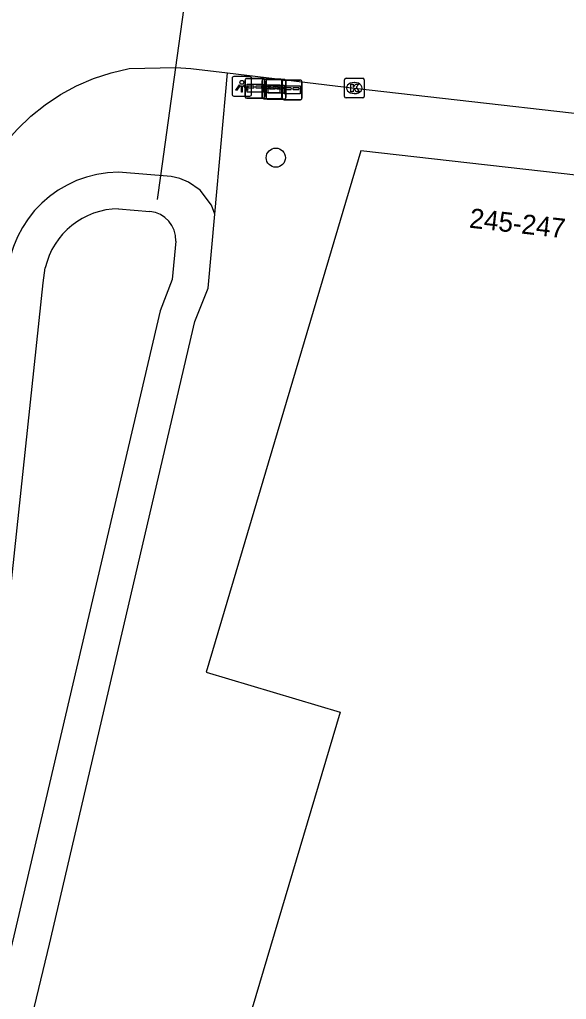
# Model space of a CAD drawing. Extents: x 161389 to 162585, y 388479 to 389761.
# Drawn here: x 162354.5 to 162382.4, y 388747.2 to 388797.2 of the extents above; entities that cross this region are included whole.
import ezdxf

# ---------------------------------------------------------------- set-up
doc = ezdxf.new("R2010")
doc.units = 0
for name, color, linetype in [('IMGEO_Berm_groen', 7, 'Continuous'), ('IMGEO_Boom', 7, 'Continuous'), ('IMGEO_Brievenbus', 7, 'Continuous'), ('IMGEO_Duiker', 7, 'Continuous'), ('IMGEO_Groenvoorziening', 7, 'Continuous'), ('IMGEO_Kolk', 7, 'Continuous'), ('IMGEO_Lichtpunt', 7, 'Continuous'), ('IMGEO_Pand', 7, 'Continuous'), ('IMGEO_Pand_nummerreeks', 7, 'Continuous'), ('IMGEO_Rijbaan_lokaal_gesloten', 7, 'Continuous'), ('IMGEO_Waterloop', 7, 'Continuous')]:
    doc.layers.add(name, color=color, linetype=linetype)

msp = doc.modelspace()

# ---------------------------------------------------------------- linework, layer by layer
at = {"layer": 'IMGEO_Berm_groen'}
for points in [[(162364.471, 388787.302), (162365.122, 388794.512)], [(162364.471, 388787.302), (162364.296, 388787.749), (162363.722, 388788.516), (162363.135, 388788.931), (162362.691, 388789.114), (162362.237, 388789.214), (162359.555, 388789.446)]]:
    msp.add_lwpolyline(points, dxfattribs=at)
msp.add_arc((162359.605, 388783.689), 5.757, 90.5023, 176.6641, dxfattribs=at)
at = {"layer": 'IMGEO_Boom'}
msp.add_circle((162367.585, 388790.182), 0.489, dxfattribs=at)
at = {"layer": 'IMGEO_Brievenbus'}
for p, q in [((162366.089, 388794.228), (162366.93, 388794.228)), ((162366.93, 388794.228), (162366.089, 388794.228)), ((162366.014, 388793.303), (162366.014, 388794.144)), ((162366.014, 388794.144), (162366.014, 388793.303)), ((162366.458, 388793.835), (162366.181, 388793.835)), ((162366.181, 388793.751), (162366.458, 388793.751)), ((162366.85, 388793.835), (162366.573, 388793.835)), ((162366.573, 388793.751), (162366.85, 388793.751)), ((162366.886, 388793.271), (162366.886, 388794.112)), ((162366.886, 388794.112), (162366.886, 388793.271)), ((162366.961, 388794.196), (162367.802, 388794.196)), ((162367.802, 388794.196), (162366.961, 388794.196)), ((162367.014, 388794.153), (162367.014, 388793.312)), ((162367.014, 388793.312), (162367.014, 388794.153)), ((162367.33, 388793.803), (162367.053, 388793.803)), ((162367.053, 388793.719), (162367.33, 388793.719)), ((162367.096, 388793.25), (162367.096, 388794.091)), ((162367.096, 388794.091), (162367.096, 388793.25)), ((162367.171, 388794.175), (162368.012, 388794.175)), ((162368.012, 388794.175), (162367.171, 388794.175)), ((162367.54, 388793.782), (162367.263, 388793.782)), ((162367.722, 388793.803), (162367.445, 388793.803)), ((162367.445, 388793.719), (162367.722, 388793.719)), ((162367.932, 388793.782), (162367.655, 388793.782)), ((162367.886, 388794.121), (162367.886, 388793.28)), ((162367.886, 388793.28), (162367.886, 388794.121)), ((162367.916, 388793.219), (162367.916, 388794.06)), ((162367.916, 388794.06), (162367.916, 388793.219)), ((162367.991, 388794.144), (162368.832, 388794.144)), ((162368.832, 388794.144), (162367.991, 388794.144)), ((162368.36, 388793.751), (162368.083, 388793.751)), ((162368.096, 388794.1), (162368.096, 388793.259)), ((162368.096, 388793.259), (162368.096, 388794.1)), ((162368.752, 388793.751), (162368.475, 388793.751)), ((162368.916, 388794.069), (162368.916, 388793.228)), ((162368.916, 388793.228), (162368.916, 388794.069)), ((162366.939, 388793.228), (162366.098, 388793.228)), ((162366.098, 388793.228), (162366.939, 388793.228)), ((162367.263, 388793.698), (162367.54, 388793.698)), ((162367.655, 388793.698), (162367.932, 388793.698)), ((162368.083, 388793.667), (162368.36, 388793.667)), ((162368.475, 388793.667), (162368.752, 388793.667)), ((162367.811, 388793.196), (162366.97, 388793.196)), ((162366.97, 388793.196), (162367.811, 388793.196)), ((162368.021, 388793.175), (162367.18, 388793.175)), ((162367.18, 388793.175), (162368.021, 388793.175)), ((162368.841, 388793.144), (162368, 388793.144)), ((162368, 388793.144), (162368.841, 388793.144))]:
    msp.add_line(p, q, dxfattribs=at)
for points in [[(162366.115, 388793.935), (162366.922, 388793.935), (162366.922, 388793.53), (162366.115, 388793.53), (162366.115, 388793.935)], [(162366.987, 388793.903), (162367.794, 388793.903), (162367.794, 388793.498), (162366.987, 388793.498), (162366.987, 388793.903)], [(162367.197, 388793.882), (162368.004, 388793.882), (162368.004, 388793.477), (162367.197, 388793.477), (162367.197, 388793.882)], [(162368.017, 388793.851), (162368.824, 388793.851), (162368.824, 388793.446), (162368.017, 388793.446), (162368.017, 388793.851)]]:
    msp.add_lwpolyline(points, dxfattribs=at)
for centre, radius, start, end in [((162366.092, 388794.15), 0.0779, 92.4484, 184.2845), ((162366.092, 388794.15), 0.0779, 92.4484, 184.2845), ((162366.936, 388794.15), 0.0779, 2.4484, 94.2845), ((162366.936, 388794.15), 0.0779, 2.4484, 94.2845), ((162366.211, 388793.793), 0.0519, 125.8089, 234.1911), ((162366.427, 388793.793), 0.0519, 305.8089, 54.1911), ((162366.604, 388793.793), 0.0519, 125.8089, 234.1911), ((162366.82, 388793.793), 0.0519, 305.8089, 54.1911), ((162366.964, 388794.118), 0.0779, 92.4484, 184.2845), ((162366.964, 388794.118), 0.0779, 92.4484, 184.2845), ((162367.083, 388793.761), 0.0519, 125.8089, 234.1911), ((162367.174, 388794.097), 0.0779, 92.4484, 184.2845), ((162367.174, 388794.097), 0.0779, 92.4484, 184.2845), ((162367.293, 388793.74), 0.0519, 125.8089, 234.1911), ((162367.299, 388793.761), 0.0519, 305.8089, 54.1911), ((162367.476, 388793.761), 0.0519, 125.8089, 234.1911), ((162367.509, 388793.74), 0.0519, 305.8089, 54.1911), ((162367.686, 388793.74), 0.0519, 125.8089, 234.1911), ((162367.692, 388793.761), 0.0519, 305.8089, 54.1911), ((162367.808, 388794.118), 0.0779, 2.4484, 94.2845), ((162367.808, 388794.118), 0.0779, 2.4484, 94.2845), ((162367.994, 388794.066), 0.0779, 92.4484, 184.2845), ((162367.994, 388794.066), 0.0779, 92.4484, 184.2845), ((162367.902, 388793.74), 0.0519, 305.8089, 54.1911), ((162368.018, 388794.097), 0.0779, 2.4484, 94.2845), ((162368.018, 388794.097), 0.0779, 2.4484, 94.2845), ((162368.113, 388793.709), 0.0519, 125.8089, 234.1911), ((162368.329, 388793.709), 0.0519, 305.8089, 54.1911), ((162368.506, 388793.709), 0.0519, 125.8089, 234.1911), ((162368.722, 388793.709), 0.0519, 305.8089, 54.1911), ((162368.838, 388794.066), 0.0779, 2.4484, 94.2845), ((162368.838, 388794.066), 0.0779, 2.4484, 94.2845), ((162366.092, 388793.306), 0.0779, 182.4484, 274.2845), ((162366.092, 388793.306), 0.0779, 182.4484, 274.2845), ((162366.964, 388793.274), 0.0779, 182.4484, 274.2845), ((162366.964, 388793.274), 0.0779, 182.4484, 274.2845), ((162366.936, 388793.306), 0.0779, 272.4484, 4.2845), ((162366.936, 388793.306), 0.0779, 272.4484, 4.2845), ((162367.174, 388793.253), 0.0779, 182.4484, 274.2845), ((162367.174, 388793.253), 0.0779, 182.4484, 274.2845), ((162367.808, 388793.274), 0.0779, 272.4484, 4.2845), ((162367.808, 388793.274), 0.0779, 272.4484, 4.2845), ((162367.994, 388793.222), 0.0779, 182.4484, 274.2845), ((162367.994, 388793.222), 0.0779, 182.4484, 274.2845), ((162368.018, 388793.253), 0.0779, 272.4484, 4.2845), ((162368.018, 388793.253), 0.0779, 272.4484, 4.2845), ((162368.838, 388793.222), 0.0779, 272.4484, 4.2845), ((162368.838, 388793.222), 0.0779, 272.4484, 4.2845)]:
    msp.add_arc(centre, radius, start, end, dxfattribs=at)
at = {"layer": 'IMGEO_Duiker'}
msp.add_lwpolyline([(162361.55, 388788.054), (162361.716, 388789.259), (162362.478, 388794.795), (162363.461, 388801.928), (162363.744, 388803.982), (162364.151, 388806.939), (162364.285, 388807.91)], dxfattribs=at)
at = {"layer": 'IMGEO_Groenvoorziening'}
msp.add_lwpolyline([(162353.626, 388739.483), (162354.058, 388741.791), (162356.029, 388750), (162363.459, 388781.811), (162364.13, 388783.523), (162364.471, 388787.302)], dxfattribs=at)
at = {"layer": 'IMGEO_Kolk'}
for p, q in [((162371.168, 388794.24), (162372.02, 388794.24)), ((162371.093, 388793.314), (162371.093, 388794.166)), ((162371.581, 388794.02), (162371.606, 388794.02)), ((162372.094, 388794.166), (162372.094, 388793.314)), ((162372.02, 388793.24), (162371.168, 388793.24)), ((162371.604, 388793.46), (162371.579, 388793.46))]:
    msp.add_line(p, q, dxfattribs=at)
for points in [[(162371.168, 388794.24), (162372.02, 388794.24)], [(162371.093, 388793.314), (162371.093, 388794.166)], [(162371.414, 388793.94), (162371.537, 388793.94), (162371.537, 388793.789), (162371.667, 388793.94), (162371.831, 388793.94), (162371.685, 388793.789), (162371.838, 388793.54), (162371.686, 388793.54), (162371.601, 388793.704), (162371.537, 388793.637), (162371.537, 388793.54), (162371.414, 388793.54), (162371.414, 388793.94)], [(162372.094, 388794.166), (162372.094, 388793.314)], [(162372.02, 388793.24), (162371.168, 388793.24)]]:
    msp.add_lwpolyline(points, dxfattribs=at)
for centre, start, end in [((162371.17, 388794.164), 91.552, 178.448), ((162371.17, 388794.164), 91.552, 178.448), ((162372.018, 388794.164), 1.552, 88.448), ((162372.018, 388794.164), 1.552, 88.448), ((162371.17, 388793.316), 181.552, 268.448), ((162371.17, 388793.316), 181.552, 268.448), ((162372.018, 388793.316), 271.552, 358.448), ((162372.018, 388793.316), 271.552, 358.448)]:
    msp.add_arc(centre, 0.0765, start, end, dxfattribs=at)
for centre, major_axis, ratio, start_param, end_param in [((162371.58, 388793.74), (-0.387, 0.002), 0.722429, 4.712389, 7.853982), ((162371.605, 388793.74), (-0.39, 0.002), 0.717154, 1.570796, 4.712389)]:
    msp.add_ellipse(centre, major_axis=major_axis, ratio=ratio, start_param=start_param, end_param=end_param, dxfattribs=at)
at = {"layer": 'IMGEO_Lichtpunt'}
for p, q in [((162365.351, 388794.234), (162365.351, 388793.427)), ((162365.351, 388794.234), (162365.351, 388793.427)), ((162366.253, 388794.329), (162365.445, 388794.329)), ((162366.253, 388794.329), (162365.445, 388794.329)), ((162366.347, 388793.427), (162366.347, 388794.234)), ((162366.347, 388793.427), (162366.347, 388794.234)), ((162365.445, 388793.333), (162366.253, 388793.333)), ((162365.445, 388793.333), (162366.253, 388793.333))]:
    msp.add_line(p, q, dxfattribs=at)
for points in [[(162365.725, 388793.898), (162365.764, 388793.87), (162365.576, 388793.608), (162365.538, 388793.635), (162365.725, 388793.898)], [(162365.827, 388793.85), (162365.874, 388793.85), (162365.874, 388793.528), (162365.827, 388793.528), (162365.827, 388793.85)], [(162365.937, 388793.87), (162365.975, 388793.897), (162366.162, 388793.635), (162366.123, 388793.607), (162365.937, 388793.87)]]:
    msp.add_lwpolyline(points, dxfattribs=at)
msp.add_circle((162365.85, 388794.032), 0.0994, dxfattribs=at)
for centre, start, end in [((162365.445, 388794.234), 90, 180), ((162365.445, 388794.234), 90, 180), ((162366.253, 388794.234), 0, 90), ((162366.253, 388794.234), 0, 90), ((162365.445, 388793.427), 180, 270), ((162365.445, 388793.427), 180, 270), ((162366.253, 388793.427), 270, 0), ((162366.253, 388793.427), 270, 360)]:
    msp.add_arc(centre, 0.0946, start, end, dxfattribs=at)
at = {"layer": 'IMGEO_Pand'}
msp.add_lwpolyline([(162391.318, 388788.343), (162371.926, 388790.534), (162364.027, 388763.89), (162370.877, 388761.846), (162363.204, 388736.022)], dxfattribs=at)
at = {"layer": 'IMGEO_Rijbaan_lokaal_gesloten'}
for points in [[(162351.586, 388785.803), (162351.754, 388786.729), (162352.005, 388787.636), (162352.335, 388788.517), (162352.742, 388789.365), (162353.224, 388790.173), (162353.776, 388790.935), (162354.394, 388791.645), (162355.073, 388792.296), (162355.807, 388792.885), (162356.591, 388793.405), (162357.418, 388793.853), (162358.282, 388794.226), (162359.176, 388794.52), (162360.092, 388794.733), (162362.478, 388794.795), (162363.253, 388794.734), (162365.122, 388794.512)], [(162365.122, 388794.512), (162371.594, 388793.742), (162388.673, 388791.789), (162398.932, 388790.608)]]:
    msp.add_lwpolyline(points, dxfattribs=at)
at = {"layer": 'IMGEO_Waterloop'}
for points in [[(162359.561, 388787.574), (162361.161, 388787.436)], [(162362.475, 388785.925), (162362.297, 388783.956), (162361.674, 388782.366), (162354.215, 388750.43), (162352.234, 388742.18), (162352.006, 388740.959), (162351.919, 388740.769), (162351.816, 388740.604), (162351.686, 388740.494), (162351.501, 388740.445), (162351.257, 388740.46), (162351.103, 388740.498), (162350.936, 388740.601), (162350.848, 388740.757), (162350.82, 388740.858), (162350.79, 388741.139), (162350.789, 388741.329), (162351.006, 388742.301), (162352.091, 388749.767), (162355.708, 388783.794)], [(162355.708, 388783.794), (162355.817, 388784.557)]]:
    msp.add_lwpolyline(points, dxfattribs=at)
for centre, radius, start, end in [((162359.604, 388783.689), 3.886, 90.6389, 167.0864), ((162361.017, 388785.984), 1.459, 357.6898, 84.3321)]:
    msp.add_arc(centre, radius, start, end, dxfattribs=at)

# ---------------------------------------------------------------- texts
at = {"layer": 'IMGEO_Pand_nummerreeks'}
msp.add_text('245-247', height=1, rotation=353.5546, dxfattribs=at).set_placement((162377.429, 388786.611))

doc.saveas('drawing.dxf')
